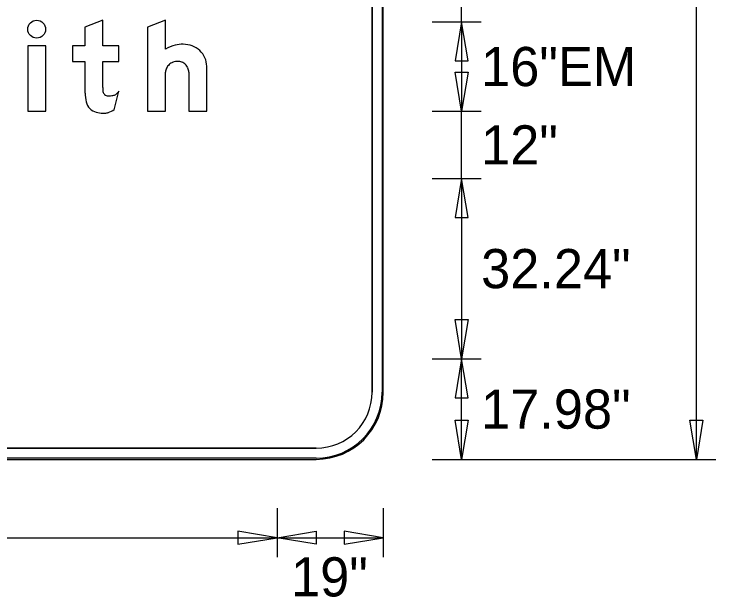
# Model space of a CAD drawing. Extents: x 2150010 to 2150174, y 145114 to 145224.
# Drawn here: x 2150041.52 to 2150051.98, y 145141.83 to 145150.52 of the extents above; entities that cross this region are included whole.
import ezdxf

# ---------------------------------------------------------------- set-up
doc = ezdxf.new("R2010")
doc.units = 0
for name, color, linetype in [('GSBWFILL', 7, 'Continuous'), ('GSCOLORFILL', 7, 'Continuous'), ('GSDIMS', 7, 'Continuous'), ('GSOUTLINE', 7, 'Continuous')]:
    doc.layers.add(name, color=color, linetype=linetype)

msp = doc.modelspace()

# ---------------------------------------------------------------- linework, layer by layer
at = {"layer": 'GSBWFILL'}
for p, q in [((2150046.853, 145156.883), (2150046.853, 145144.883)), ((2150047.02, 145144.883), (2150047.02, 145156.883)), ((2150043.01, 145149.092), (2150043.08, 145149.368)), ((2150046.02, 145144.05), (2150032.522, 145144.05)), ((2150032.522, 145143.883), (2150046.02, 145143.883))]:
    msp.add_line(p, q, dxfattribs=at)
for points in [[(2150042.84, 145149.421), (2150042.84, 145149.811), (2150043.08, 145149.811), (2150043.08, 145150.041), (2150042.84, 145150.041), (2150042.84, 145150.424), (2150042.573, 145150.323), (2150042.573, 145150.041), (2150042.387, 145150.041), (2150042.387, 145149.811), (2150042.573, 145149.811), (2150042.573, 145149.34)], [(2150043.773, 145149.993), (2150043.773, 145150.424), (2150043.507, 145150.321), (2150043.507, 145149.068), (2150043.773, 145149.068), (2150043.773, 145149.652)], [(2150044.12, 145149.652), (2150044.12, 145149.068), (2150044.387, 145149.068), (2150044.387, 145149.74)]]:
    msp.add_lwpolyline(points, dxfattribs=at)
msp.add_lwpolyline([(2150041.72, 145149.068), (2150041.987, 145149.068), (2150041.987, 145150.041), (2150041.72, 145150.041)], close=True, dxfattribs=at)
for centre, radius, start, end in [((2150044.036, 145149.534), 0.533, 90, 102.6043), ((2150044.036, 145149.692), 0.375, 68.8636, 90), ((2150044.031, 145149.588), 0.48, 103.4695, 122.4943), ((2150044.045, 145149.716), 0.35, 46.975, 68.8636), ((2150044.059, 145149.731), 0.33, 23.9317, 46.975), ((2150044.081, 145149.74), 0.306, 0, 23.9317), ((2150043.934, 145149.642), 0.162, 131.0076, 154.5283), ((2150043.947, 145149.626), 0.183, 109.8074, 131.0076), ((2150043.956, 145149.602), 0.21, 90, 109.8074), ((2150043.956, 145149.643), 0.168, 68.0808, 90), ((2150043.958, 145149.648), 0.164, 45.8298, 68.0808), ((2150043.961, 145149.651), 0.159, 23.0928, 45.8298), ((2150043.912, 145149.652), 0.139, 154.5283, 180), ((2150043.965, 145149.652), 0.155, 0, 23.0928), ((2150046.02, 145144.883), 1, 270, 0), ((2150046.02, 145144.883), 0.833, 270, 0)]:
    msp.add_arc(centre, radius, start, end, dxfattribs=at)
msp.add_ellipse((2150041.853, 145150.291), major_axis=(0, 0.133), ratio=0.999983, dxfattribs=at)
for centre, major_axis, start_param, end_param in [((2150043.091, 145149.34), (0, 0.517), 1.570796, 1.830698), ((2150044.509, 145149.421), (0, 1.669), 1.570796, 1.606005), ((2150042.917, 145149.375), (0, 0.0767), 1.74085, 2.407828), ((2150042.905, 145149.499), (0, 0.219), 3.756278, 4.071638), ((2150042.919, 145149.378), (0, 0.0803), 2.407828, 3.141593), ((2150042.919, 145149.719), (0, 0.421), 3.141593, 3.310762), ((2150042.973, 145149.402), (0, 0.1), 3.310762, 3.756278), ((2150042.8, 145149.263), (0, 0.217), 1.830698, 2.869526), ((2150042.84, 145149.406), (0, 0.365), 2.869526, 3.141593), ((2150042.84, 145149.567), (0, 0.526), 3.141593, 3.205734), ((2150042.86, 145149.258), (0, 0.217), 3.205734, 3.427755), ((2150042.831, 145149.355), (0, 0.317), 3.427755, 3.738844)]:
    msp.add_ellipse(centre, major_axis=major_axis, ratio=0.99999, start_param=start_param, end_param=end_param, dxfattribs=at)
at = {"layer": 'GSCOLORFILL'}
for p, q in [((2150046.853, 145156.883), (2150046.853, 145144.883)), ((2150047.003, 145156.883), (2150047.003, 145144.883)), ((2150047.02, 145144.883), (2150047.02, 145156.883)), ((2150047.02, 145144.883), (2150047.02, 145156.883)), ((2150047.02, 145144.883), (2150047.02, 145156.883)), ((2150043.01, 145149.092), (2150043.08, 145149.368)), ((2150046.02, 145144.05), (2150032.522, 145144.05)), ((2150046.02, 145143.9), (2150032.52, 145143.9)), ((2150032.52, 145143.883), (2150046.02, 145143.883)), ((2150032.52, 145143.883), (2150046.02, 145143.883)), ((2150032.522, 145143.883), (2150046.02, 145143.883))]:
    msp.add_line(p, q, dxfattribs=at)
for points in [[(2150042.84, 145149.421), (2150042.84, 145149.811), (2150043.08, 145149.811), (2150043.08, 145150.041), (2150042.84, 145150.041), (2150042.84, 145150.424), (2150042.573, 145150.323), (2150042.573, 145150.041), (2150042.387, 145150.041), (2150042.387, 145149.811), (2150042.573, 145149.811), (2150042.573, 145149.34)], [(2150043.773, 145149.993), (2150043.773, 145150.424), (2150043.507, 145150.321), (2150043.507, 145149.068), (2150043.773, 145149.068), (2150043.773, 145149.652)], [(2150044.12, 145149.652), (2150044.12, 145149.068), (2150044.387, 145149.068), (2150044.387, 145149.74)]]:
    msp.add_lwpolyline(points, dxfattribs=at)
msp.add_lwpolyline([(2150041.72, 145149.068), (2150041.987, 145149.068), (2150041.987, 145150.041), (2150041.72, 145150.041)], close=True, dxfattribs=at)
for centre, radius, start, end in [((2150044.036, 145149.534), 0.533, 90, 102.6043), ((2150044.036, 145149.692), 0.375, 68.8636, 90), ((2150044.031, 145149.588), 0.48, 103.4695, 122.4943), ((2150044.045, 145149.716), 0.35, 46.975, 68.8636), ((2150044.059, 145149.731), 0.33, 23.9317, 46.975), ((2150044.081, 145149.74), 0.306, 0, 23.9317), ((2150043.934, 145149.642), 0.162, 131.0076, 154.5283), ((2150043.947, 145149.626), 0.183, 109.8074, 131.0076), ((2150043.956, 145149.602), 0.21, 90, 109.8074), ((2150043.956, 145149.643), 0.168, 68.0808, 90), ((2150043.958, 145149.648), 0.164, 45.8298, 68.0808), ((2150043.961, 145149.651), 0.159, 23.0928, 45.8298), ((2150043.912, 145149.652), 0.139, 154.5283, 180), ((2150043.965, 145149.652), 0.155, 0, 23.0928), ((2150046.02, 145144.883), 1, 270, 0), ((2150046.02, 145144.883), 1, 270, 0), ((2150046.02, 145144.883), 0.833, 270, 0), ((2150046.02, 145144.883), 1, 270, 0), ((2150046.02, 145144.883), 0.983, 270, 0)]:
    msp.add_arc(centre, radius, start, end, dxfattribs=at)
msp.add_ellipse((2150041.853, 145150.291), major_axis=(0, 0.133), ratio=0.999983, dxfattribs=at)
for centre, major_axis, start_param, end_param in [((2150043.091, 145149.34), (0, 0.517), 1.570796, 1.830698), ((2150044.509, 145149.421), (0, 1.669), 1.570796, 1.606005), ((2150042.917, 145149.375), (0, 0.0767), 1.74085, 2.407828), ((2150042.905, 145149.499), (0, 0.219), 3.756278, 4.071638), ((2150042.919, 145149.378), (0, 0.0803), 2.407828, 3.141593), ((2150042.919, 145149.719), (0, 0.421), 3.141593, 3.310762), ((2150042.973, 145149.402), (0, 0.1), 3.310762, 3.756278), ((2150042.8, 145149.263), (0, 0.217), 1.830698, 2.869526), ((2150042.84, 145149.406), (0, 0.365), 2.869526, 3.141593), ((2150042.84, 145149.567), (0, 0.526), 3.141593, 3.205734), ((2150042.86, 145149.258), (0, 0.217), 3.205734, 3.427755), ((2150042.831, 145149.355), (0, 0.317), 3.427755, 3.738844)]:
    msp.add_ellipse(centre, major_axis=major_axis, ratio=0.99999, start_param=start_param, end_param=end_param, dxfattribs=at)
at = {"layer": 'GSDIMS'}
for p, q in [((2150048.187, 145150.401), (2150048.187, 145151.401)), ((2150051.687, 145143.883), (2150051.687, 145151.401)), ((2150047.749, 145150.401), (2150048.478, 145150.401)), ((2150047.749, 145150.401), (2150048.478, 145150.401)), ((2150048.187, 145150.401), (2150048.187, 145149.068)), ((2150047.749, 145149.068), (2150048.478, 145149.068)), ((2150047.749, 145149.068), (2150048.478, 145149.068)), ((2150048.187, 145148.068), (2150048.187, 145149.068)), ((2150047.749, 145148.068), (2150048.478, 145148.068)), ((2150047.749, 145148.068), (2150048.478, 145148.068)), ((2150048.187, 145148.068), (2150048.187, 145145.381)), ((2150047.749, 145145.381), (2150048.478, 145145.381)), ((2150047.749, 145145.381), (2150048.478, 145145.381)), ((2150048.187, 145143.883), (2150048.187, 145145.381)), ((2150047.749, 145143.883), (2150048.478, 145143.883)), ((2150047.749, 145143.883), (2150051.249, 145143.883)), ((2150051.249, 145143.883), (2150051.978, 145143.883)), ((2150045.437, 145143.154), (2150045.437, 145142.425)), ((2150045.437, 145143.154), (2150045.437, 145142.425)), ((2150047.02, 145143.154), (2150047.02, 145142.425)), ((2150047.02, 145143.154), (2150047.02, 145142.425)), ((2150033.103, 145142.716), (2150045.437, 145142.716)), ((2150045.437, 145142.716), (2150047.02, 145142.716))]:
    msp.add_line(p, q, dxfattribs=at)
for points in [[(2150048.187, 145150.401), (2150048.09, 145149.818), (2150048.284, 145149.818)], [(2150048.187, 145149.068), (2150048.09, 145149.651), (2150048.284, 145149.651)], [(2150048.187, 145148.068), (2150048.09, 145147.484), (2150048.284, 145147.484)], [(2150048.187, 145145.381), (2150048.09, 145145.965), (2150048.284, 145145.965)], [(2150048.187, 145145.381), (2150048.09, 145144.798), (2150048.284, 145144.798)], [(2150048.187, 145143.883), (2150048.09, 145144.466), (2150048.284, 145144.466)], [(2150051.687, 145143.883), (2150051.59, 145144.466), (2150051.784, 145144.466)], [(2150045.437, 145142.716), (2150044.853, 145142.813), (2150044.853, 145142.619)], [(2150045.437, 145142.716), (2150046.02, 145142.813), (2150046.02, 145142.619)], [(2150047.02, 145142.716), (2150046.437, 145142.813), (2150046.437, 145142.619)]]:
    msp.add_lwpolyline(points, close=True, dxfattribs=at)
at = {"layer": 'GSOUTLINE'}
for p, q in [((2150046.853, 145144.883), (2150046.853, 145156.883)), ((2150047.02, 145144.883), (2150047.02, 145156.883)), ((2150043.01, 145149.092), (2150043.08, 145149.368)), ((2150032.52, 145144.05), (2150046.02, 145144.05)), ((2150032.52, 145143.883), (2150046.02, 145143.883))]:
    msp.add_line(p, q, dxfattribs=at)
for points in [[(2150042.84, 145149.421), (2150042.84, 145149.811), (2150043.08, 145149.811), (2150043.08, 145150.041), (2150042.84, 145150.041), (2150042.84, 145150.424), (2150042.573, 145150.323), (2150042.573, 145150.041), (2150042.387, 145150.041), (2150042.387, 145149.811), (2150042.573, 145149.811), (2150042.573, 145149.34)], [(2150043.773, 145149.993), (2150043.773, 145150.424), (2150043.507, 145150.321), (2150043.507, 145149.068), (2150043.773, 145149.068), (2150043.773, 145149.652)], [(2150044.12, 145149.652), (2150044.12, 145149.068), (2150044.387, 145149.068), (2150044.387, 145149.74)]]:
    msp.add_lwpolyline(points, dxfattribs=at)
msp.add_lwpolyline([(2150041.72, 145149.068), (2150041.987, 145149.068), (2150041.987, 145150.041), (2150041.72, 145150.041)], close=True, dxfattribs=at)
for centre, radius, start, end in [((2150044.036, 145149.534), 0.533, 90, 102.6043), ((2150044.036, 145149.692), 0.375, 68.8636, 90), ((2150044.031, 145149.588), 0.48, 103.4695, 122.4943), ((2150044.045, 145149.716), 0.35, 46.975, 68.8636), ((2150044.059, 145149.731), 0.33, 23.9317, 46.975), ((2150044.081, 145149.74), 0.306, 0, 23.9317), ((2150043.934, 145149.642), 0.162, 131.0076, 154.5283), ((2150043.947, 145149.626), 0.183, 109.8074, 131.0076), ((2150043.956, 145149.602), 0.21, 90, 109.8074), ((2150043.956, 145149.643), 0.168, 68.0808, 90), ((2150043.958, 145149.648), 0.164, 45.8298, 68.0808), ((2150043.961, 145149.651), 0.159, 23.0928, 45.8298), ((2150043.912, 145149.652), 0.139, 154.5283, 180), ((2150043.965, 145149.652), 0.155, 0, 23.0928), ((2150046.02, 145144.883), 1, 270, 0), ((2150046.02, 145144.883), 0.833, 270, 0)]:
    msp.add_arc(centre, radius, start, end, dxfattribs=at)
msp.add_ellipse((2150041.853, 145150.291), major_axis=(0, 0.133), ratio=0.999983, dxfattribs=at)
for centre, major_axis, start_param, end_param in [((2150043.091, 145149.34), (0, 0.517), 1.570796, 1.830698), ((2150044.509, 145149.421), (0, 1.669), 1.570796, 1.606005), ((2150042.917, 145149.375), (0, 0.0767), 1.74085, 2.407828), ((2150042.905, 145149.499), (0, 0.219), 3.756278, 4.071638), ((2150042.919, 145149.378), (0, 0.0803), 2.407828, 3.141593), ((2150042.919, 145149.719), (0, 0.421), 3.141593, 3.310762), ((2150042.973, 145149.402), (0, 0.1), 3.310762, 3.756278), ((2150042.8, 145149.263), (0, 0.217), 1.830698, 2.869526), ((2150042.84, 145149.406), (0, 0.365), 2.869526, 3.141593), ((2150042.84, 145149.567), (0, 0.526), 3.141593, 3.205734), ((2150042.86, 145149.258), (0, 0.217), 3.205734, 3.427755), ((2150042.831, 145149.355), (0, 0.317), 3.427755, 3.738844)]:
    msp.add_ellipse(centre, major_axis=major_axis, ratio=0.99999, start_param=start_param, end_param=end_param, dxfattribs=at)

# ---------------------------------------------------------------- texts
at = {"layer": 'GSDIMS'}
for s, p in [('16"EM', (2150048.478, 145149.443)), ('12"', (2150048.478, 145148.276)), ('32.24"', (2150048.478, 145146.433)), ('17.98"', (2150048.478, 145144.34)), ('19"', (2150045.645, 145141.841))]:
    msp.add_text(s, height=0.5833, dxfattribs=at).set_placement(p)

doc.saveas('drawing.dxf')
